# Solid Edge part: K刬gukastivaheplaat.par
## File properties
Author: Türk
Template: Iso Part.par
Last saved by: Türk
Revision: 1
Application: Solid Edge
Accuracy: 0,990
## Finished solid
Body 1: solid body, 11 faces, 26 edges, 16 vertices.
  Faces by surface: plane 6, cylinder 5
  Edges by curve: line 16, circle 10
Bounding box of the edges (mm): 250.000 x 10.000 x 250.000, from (-125, 0, -125) to (125, 10, 125).
Cylindrical faces by radius (mm): R20 x1, R50 x3, R115 x1
Planar faces by outward normal: +x 1, +y 1, +z 1, -x 1, -y 1, -z 1
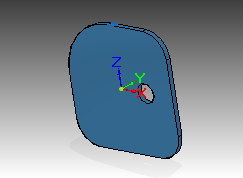
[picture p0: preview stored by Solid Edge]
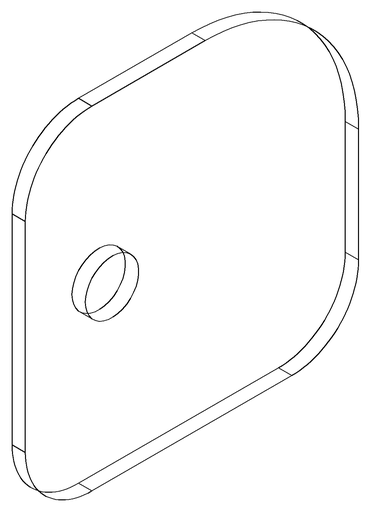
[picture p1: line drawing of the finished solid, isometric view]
